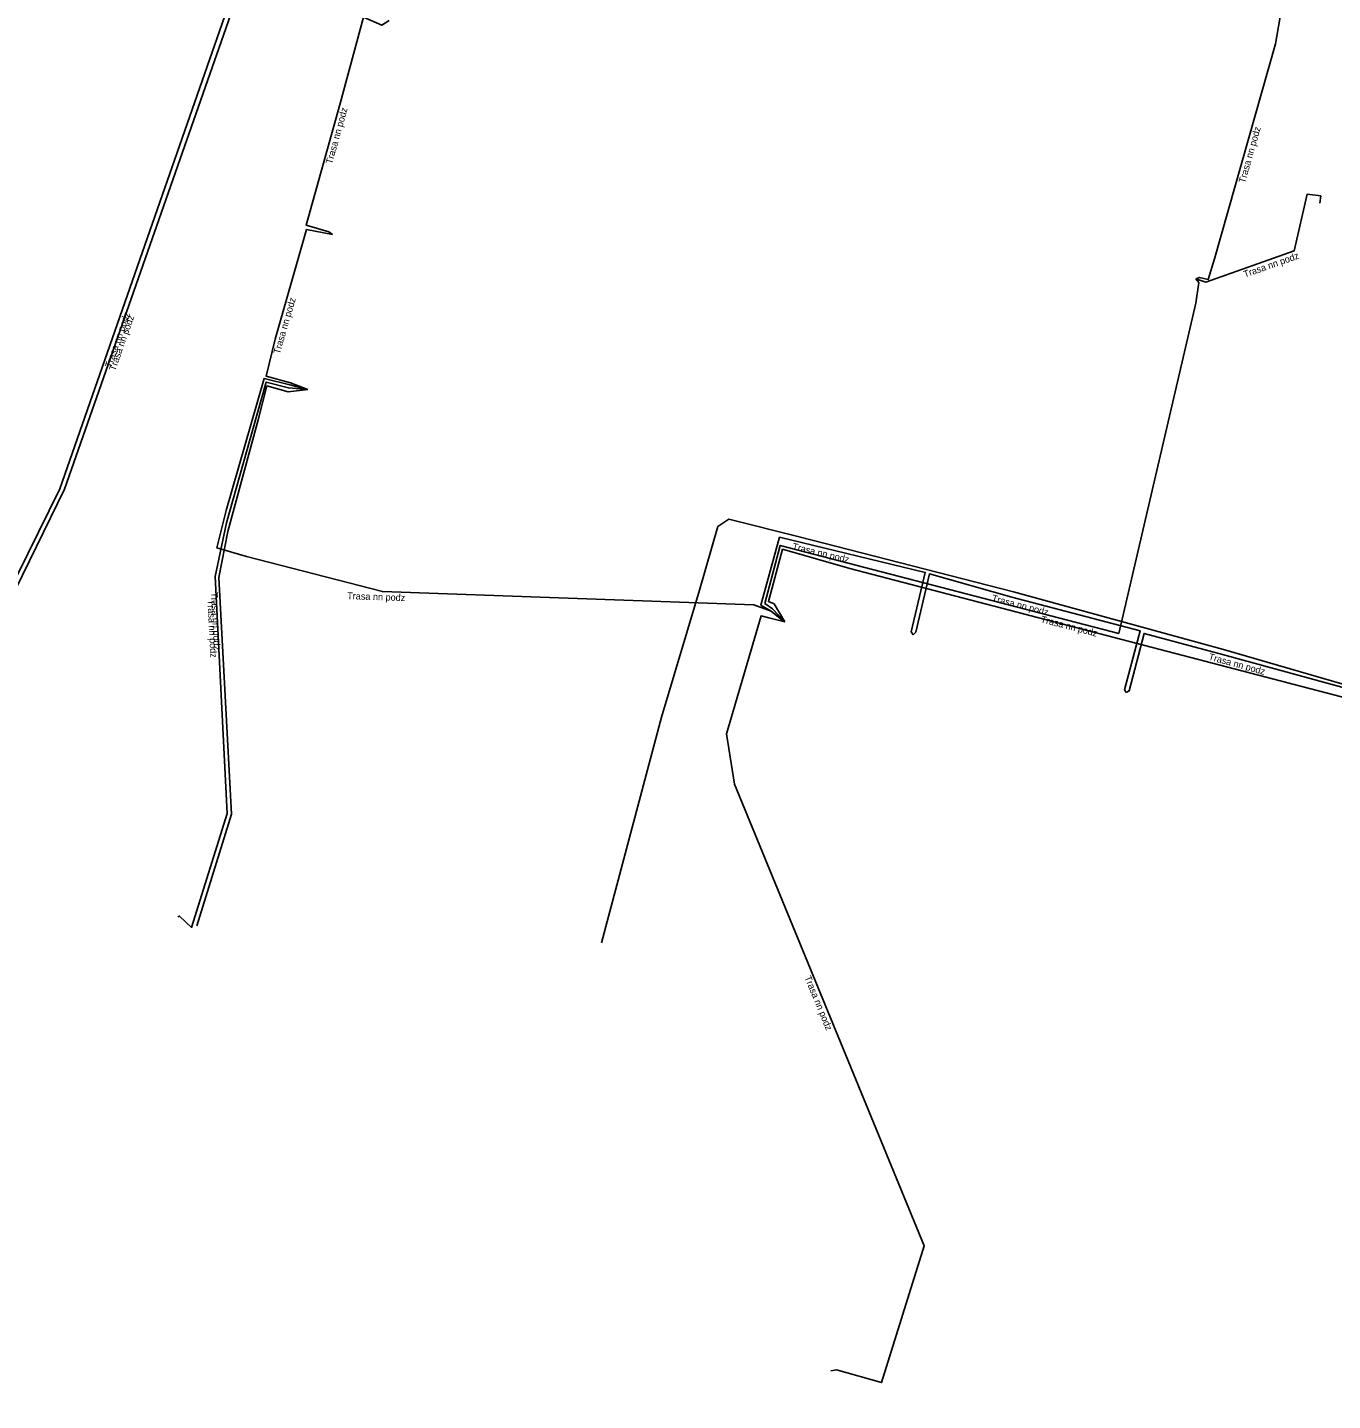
# Model space of a CAD drawing. Extents: x -843786 to -842968, y -1003095 to -1002172.
# Drawn here: x -843451.5 to -843355.5, y -1003000.3 to -1002899.3 of the extents above; entities that cross this region are included whole.
import ezdxf

# ---------------------------------------------------------------- set-up
doc = ezdxf.new("R2010")
doc.units = 0
for name, color, linetype in [('Spojnice NN', 7, 'Continuous'), ('Spojnice VN', 7, 'Continuous'), ('Vrstva 20', 7, 'Continuous')]:
    doc.layers.add(name, color=color, linetype=linetype)

msp = doc.modelspace()

# ---------------------------------------------------------------- linework, layer by layer
at = {"layer": 'Spojnice NN'}
for points in [[(-843458.03, -1002952.19), (-843448.76, -1002933.29), (-843433.14, -1002888.67), (-843424.54, -1002872.49), (-843409.8, -1002832.82), (-843409.54, -1002828.37), (-843411.41, -1002814.78), (-843417.24, -1002813.94), (-843435.17, -1002807.76), (-843436.68, -1002809.11), (-843443.13, -1002830.64), (-843444.71, -1002835.49), (-843464.18, -1002828.76)], [(-843458.52, -1002952.33), (-843449.11, -1002933.26), (-843433.49, -1002888.46), (-843424.89, -1002872.39), (-843410.1, -1002832.76), (-843409.84, -1002828.38), (-843411.68, -1002815.05), (-843417.31, -1002814.24), (-843435.1, -1002808.1), (-843436.41, -1002809.28), (-843442.84, -1002830.73), (-843444.52, -1002835.87), (-843464.56, -1002828.95)], [(-843365.56, -1002917.8), (-843365.28, -1002917.71), (-843364.64, -1002917.86), (-843364.19, -1002916.34), (-843359.7, -1002900.52), (-843359.15, -1002897.42), (-843359.98, -1002897.2), (-843360.2, -1002897.08)], [(-843424.88, -1002898.81), (-843425.43, -1002899.17), (-843426.76, -1002898.58), (-843428.5, -1002904.91), (-843430.99, -1002913.87), (-843429.33, -1002914.36), (-843429.06, -1002914.56)], [(-843365.56, -1002917.8), (-843364.82, -1002918.05), (-843358.33, -1002915.76), (-843357.37, -1002911.59), (-843356.37, -1002911.72), (-843356.44, -1002912.24)], [(-843429.06, -1002914.56), (-843430.96, -1002914.19), (-843433.28, -1002922.24), (-843433.92, -1002924.98), (-843432.14, -1002925.45), (-843430.87, -1002925.94)], [(-843395.79, -1002943.04), (-843396.68, -1002942.08), (-843397.25, -1002941.69), (-843396.12, -1002937.42), (-843371.22, -1002943.89), (-843365.56, -1002919.61), (-843365.34, -1002918.09), (-843365.56, -1002917.8)], [(-843430.87, -1002925.94), (-843432.3, -1002925.83), (-843433.92, -1002925.4), (-843434.62, -1002927.83), (-843436.84, -1002935.76), (-843437.69, -1002939.71), (-843436.79, -1002957.13), (-843439.42, -1002965.51), (-843440.3, -1002964.67), (-843440.42, -1002964.72)], [(-843430.87, -1002925.94), (-843432.32, -1002926.13), (-843433.88, -1002925.68), (-843434.52, -1002928.18), (-843436.74, -1002936.4), (-843437.41, -1002939.78), (-843436.49, -1002957.18), (-843439.03, -1002965.4)], [(-843430.87, -1002925.94), (-843432.19, -1002925.6), (-843434.09, -1002925.15), (-843436.88, -1002934.84), (-843437.55, -1002937.59), (-843435.38, -1002938.23), (-843425.38, -1002940.81), (-843398.07, -1002941.79), (-843396.78, -1002942.26), (-843395.85, -1002943.01), (-843395.79, -1002943.04)], [(-843386.35, -1002943.99), (-843386.5, -1002943.76), (-843385.46, -1002939.4), (-843396.17, -1002936.82), (-843397.55, -1002941.8), (-843396.78, -1002942.26), (-843395.79, -1002943.04)], [(-843395.79, -1002943.04), (-843396.58, -1002941.7), (-843396.99, -1002941.55), (-843395.95, -1002937.7), (-843391.01, -1002939.1), (-843352.13, -1002949.25), (-843331, -1002954.79), (-843291.14, -1002965.23), (-843282.84, -1002967.54), (-843283.78, -1002971.27), (-843285.71, -1002981.8), (-843290.81, -1003000.3), (-843302.5, -1002997.08), (-843303.04, -1002997)], [(-843370.69, -1002948.22), (-843370.8, -1002948.04), (-843369.64, -1002943.69), (-843379.08, -1002941.23), (-843385.15, -1002939.51), (-843386.16, -1002943.8), (-843386.35, -1002943.99)], [(-843395.79, -1002943.04), (-843396.95, -1002942.73), (-843397.53, -1002942.6), (-843400.07, -1002951.27), (-843399.49, -1002954.98), (-843385.54, -1002988.93), (-843388.67, -1002998.97), (-843391.99, -1002998.05), (-843392.39, -1002998.11)], [(-843354.64, -1002952.65), (-843354.71, -1002952.42), (-843353.56, -1002948.18), (-843363.6, -1002945.44), (-843369.36, -1002943.89), (-843370.45, -1002948.11), (-843370.69, -1002948.22)]]:
    msp.add_lwpolyline(points, dxfattribs=at)
at = {"layer": 'Spojnice VN'}
msp.add_lwpolyline([(-843409.28, -1002966.63), (-843404.85, -1002950.05), (-843402.07, -1002940.71), (-843400.7, -1002936.03), (-843399.91, -1002935.49), (-843394.72, -1002936.79), (-843378.96, -1002940.83), (-843363.52, -1002945.08), (-843348.23, -1002949.51), (-843333.59, -1002953.29), (-843318.16, -1002957.04), (-843303.02, -1002961.19), (-843286.77, -1002965.44), (-843283.2, -1002966.33), (-843284.47, -1002971.37), (-843286.59, -1002981.4), (-843292, -1002984.45), (-843294.02, -1002984.07), (-843295.78, -1002983.43)], dxfattribs=at)

# ---------------------------------------------------------------- texts
at = {"layer": 'Vrstva 20'}
for rotation, p in [(74.4689, (-843429.08, -1002909.41)), (74.1755, (-843361.94, -1002910.81)), (19.4615, (-843361.95, -1002917.73)), (73.9029, (-843432.93, -1002923.38)), (70.7845, (-843445.33, -1002924.39)), (70.7139, (-843445.03, -1002924.62)), (346.4982, (-843395.27, -1002937.71)), (273.009, (-843438, -1002940.86)), (357.9313, (-843427.98, -1002941.36)), (345.3978, (-843380.6, -1002941.51)), (272.946, (-843438.25, -1002941.42)), (345.4274, (-843377, -1002943.06)), (344.7446, (-843364.66, -1002945.82)), (292.3302, (-843394.35, -1002969.18))]:
    msp.add_text('Trasa nn podz', height=0.5, rotation=rotation, dxfattribs=at).set_placement(p)

doc.saveas('drawing.dxf')
